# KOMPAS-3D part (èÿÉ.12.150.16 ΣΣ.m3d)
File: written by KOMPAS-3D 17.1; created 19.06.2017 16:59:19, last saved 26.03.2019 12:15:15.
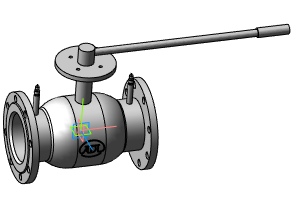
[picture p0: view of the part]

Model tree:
1. Операция без истории:2  (labels: Сталь 20  ГОСТ 1050-88)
